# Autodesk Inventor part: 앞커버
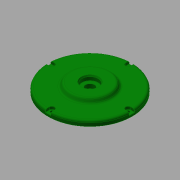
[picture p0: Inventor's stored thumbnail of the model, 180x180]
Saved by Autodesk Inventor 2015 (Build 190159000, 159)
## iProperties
Created: 2016-11
Part Number: 앞커버
Material: 알루미늄 6061
Document SubType Name: Modeling
Designer: mduedu
Density: 2.71 g/cm^3
Mass: 394.828 g
Surface Area: 366.341 cm^2
Volume: 145.693 cm^3
Appearance: 진녹색
Author: mduedu
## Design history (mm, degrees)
sketch "스케치1"
  geometry: L1 (22, -12.5)-(22, -30); L2 (22, -30)-(16, -33.464); L3 (16, -33.464)-(16, -65); L4 (16, -65)-(8, -65); L5 (8, -65)-(8, -53); L6 (8, -53)-(0, -53); L7 (0, -53)-(0, -14); L8 (0, 0)-(22, 0); L9 (8, -14)-(8, -7); L10 (8, -7)-(14.5, -7); L11 (14.5, -7)-(14.5, -12.5); L12 (0, -14)-(8, -14); L13 (14.5, -12.5)-(22, -12.5)
  constraints: 26 end point, 8 parallel, 3 perpendicular, 2 horizontal, 2 vertical alignment, 1 collinear
  dimensions: "d0" = 8 distance of L5.end L6.end; "d2" = 8 distance of L3.end L4.end; "d3" = 6 distance between parallel lines of L1 L3; "d4" = 120 deg angle of L3 L2; "d5" = 7.5 distance of L11.end L1.start; "d6" = 60 diameter of L1.end L8; "d7" = 14 diameter of L10 L8; "d8" = 28 diameter of L12 L8; "d9" = 25 diameter of L13 L8; "d10" = 106 diameter of L6 L8; "d11" = 130 diameter of L4 L8
revolve "회전1" sketch "스케치1" stored, may be unused: angle "d12" = 90 deg
fillet "모깎기1" dims "d13" = 0.3
fillet "모깎기2" dims "d14" = 3
chamfer "모따기1" distance "d15" = 1; stored, may be unused: second distance "d16" = 2, angle "d17" = 45 deg
fillet "모깎기3" dims "d18" = 0.3
chamfer "모따기2" distance "d36" = 2; stored, may be unused: second distance "d37" = 2, angle "d38" = 30 deg
sketch "스케치3"
  geometry: C1 r 65 at (0, 0) reference; A1 r 59 centre (0, 0) between (0, 59) and (59, 0); 2 further points
  constraints: 4 point on circle, 2 horizontal alignment, 2 vertical alignment, 1 centre point, 1 coincident
  dimensions: "d33" = 118 diameter of A1
sketch "스케치4"
  geometry: 4 further points
  constraints: 4 other
hole "구멍2" sketch "스케치4" at (0, 59), (-59, 0), (59, 0), (0, -59) diameter "d39" = 4.5; stored, may be unused: countersink angle "d43" = 90 deg, drill point angle "d45" = 0 deg; dims "d40" = 6, "d41" = 8, "d42" = 4.6, "d44" = 8
sketch "스케치6"
  geometry: L1 (-4, 5.877)-(-4, 0); L2 (4, 5.877)-(4, 0); A1 r 4 centre (0, 0) between (-2.712, 2.941) and (2.712, 2.941) reference; A2 r 65 centre (0, -59) between (-4, 5.877) and (4, 5.877) reference; 1 further point
  constraints: 4 end point, 4 point on circle, 2 tangent, 2 vertical
extrude "돌출2" cut sketch "스케치6" stored distance "d51" = 10; taper "d52" = 0 deg
fillet "모깎기5" dims "d56" = 0.3
fillet "모깎기6" dims "d57" = 0.3
sketch "스케치5"
  geometry: C1 r 22 at (0, 0); C2 r 45 at (0, 0); 1 further point
  constraints: 2 centre point, 2 coincident
  dimensions: "d46" = 44 diameter of C1; "d47" = 90 diameter of C2
extrude "돌출1" cut sketch "스케치5" distance "d48" = 8; taper "d49" = 0 deg
fillet "모깎기4" dims "d50" = 3
node "솔리드1"
pattern_circular "원형 패턴1" dims angle "d54" = 360 deg
pattern_circular "원형 패턴2" dims angle "d59" = 360 deg
pattern_circular "원형 패턴3" dims angle "d62" = 360 deg
